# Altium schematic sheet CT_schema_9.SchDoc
size 274 x 160 mm
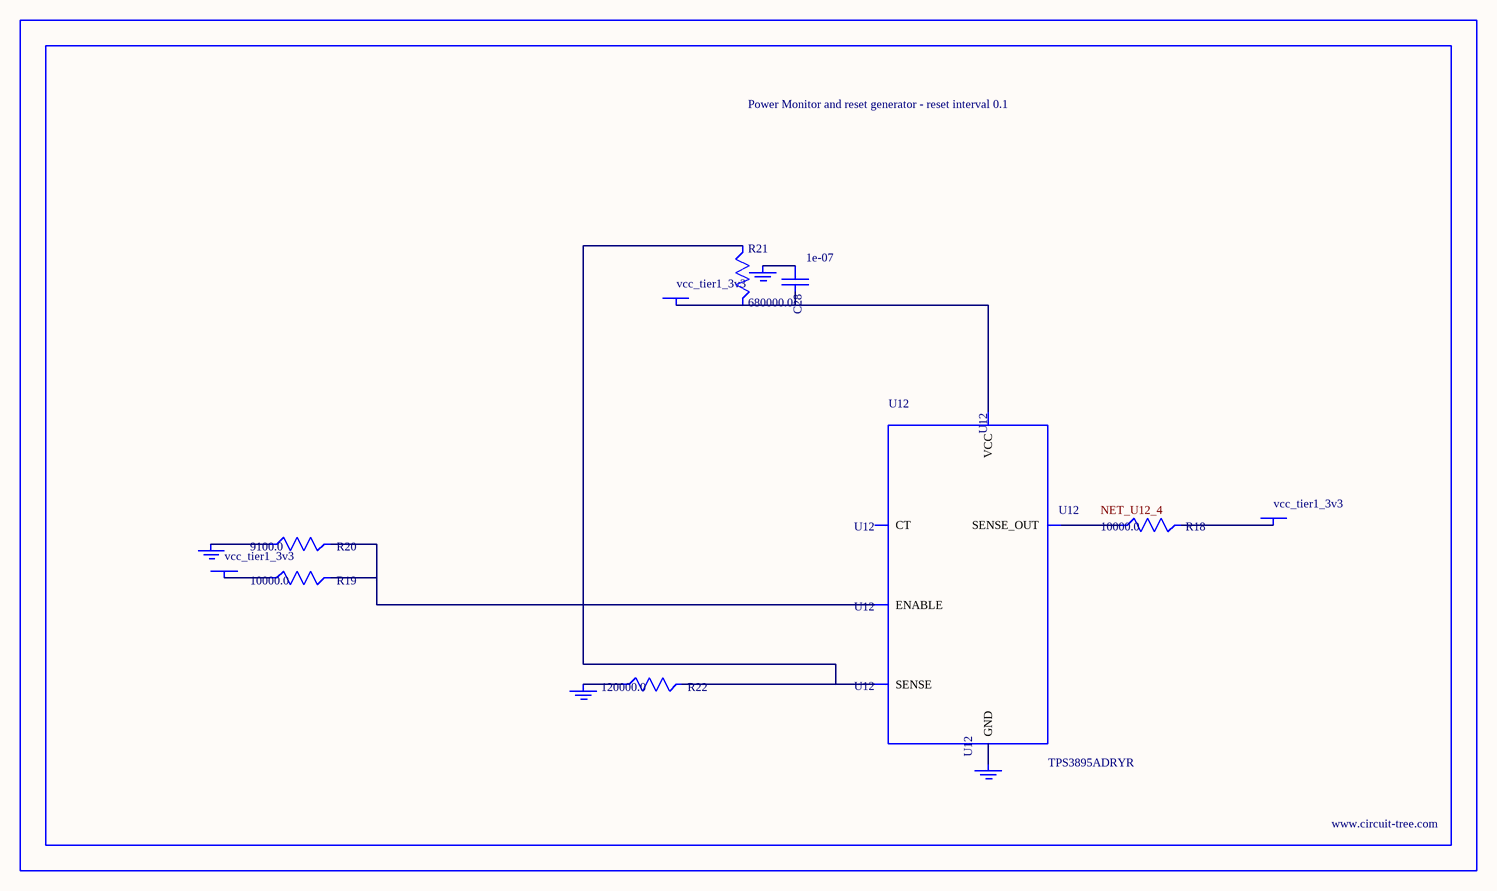
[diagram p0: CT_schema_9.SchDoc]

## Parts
BORDER8  (no value)
C28  1e-07  [C0402]
GND_INSTANCE_8_0  (no value)
GND_INSTANCE_8_1  (no value)
GND_INSTANCE_8_2  (no value)
GND_INSTANCE_8_3  (no value)
POWER_INSTANCE_8_0  vcc_tier1_3v3
POWER_INSTANCE_8_1  vcc_tier1_3v3
POWER_INSTANCE_8_2  vcc_tier1_3v3
R18  10000.0  [R0603]
R19  10000.0  [R0603]
R20  9100.0  [R0603]
R21  680000.0  [R0603]
R22  120000.0  [R0603]
U12  TPS3895ADRYR  [SON-6]

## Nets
NetC28_1: C28.1 GND_INSTANCE_8_2.0(GND)
NetC28_2: C28.2 POWER_INSTANCE_8_2.0(PWR) R21.2 U12.6(VCC)
NetGND_INSTANCE_8_0_0: GND_INSTANCE_8_0.0(GND) R20.1
NetGND_INSTANCE_8_1_0: GND_INSTANCE_8_1.0(GND) R22.1
NetGND_INSTANCE_8_3_0: GND_INSTANCE_8_3.0(GND) U12.2(GND)
NetPOWER_INSTANCE_8_0_0: POWER_INSTANCE_8_0.0(PWR) R19.1
NetPOWER_INSTANCE_8_1_0: POWER_INSTANCE_8_1.0(PWR) R18.2
NetR18_1: R18.1 U12.4(SENSE_OUT)
NetR19_2: R19.2 R20.2 U12.1(ENABLE)
NetR21_1: R21.1 R22.2 U12.3(SENSE)

Not connected (* = marked no-connect by the designer): U12 5(CT)

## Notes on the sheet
- Labels drawn without touching a wire or pin: NET_U12_4

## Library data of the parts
BORDER8 = BORDER_PAGE8
C28 = C0402C104K3RACTU
GND_INSTANCE_8_0-GND_INSTANCE_8_3 = GND
POWER_INSTANCE_8_0-POWER_INSTANCE_8_2 = PWR
R18 R19 = RC0603JR-0710KL
R20 = RC0603JR-079K1L
R21 = RC0603JR-07680KL
R22 = RC0603JR-07120KL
